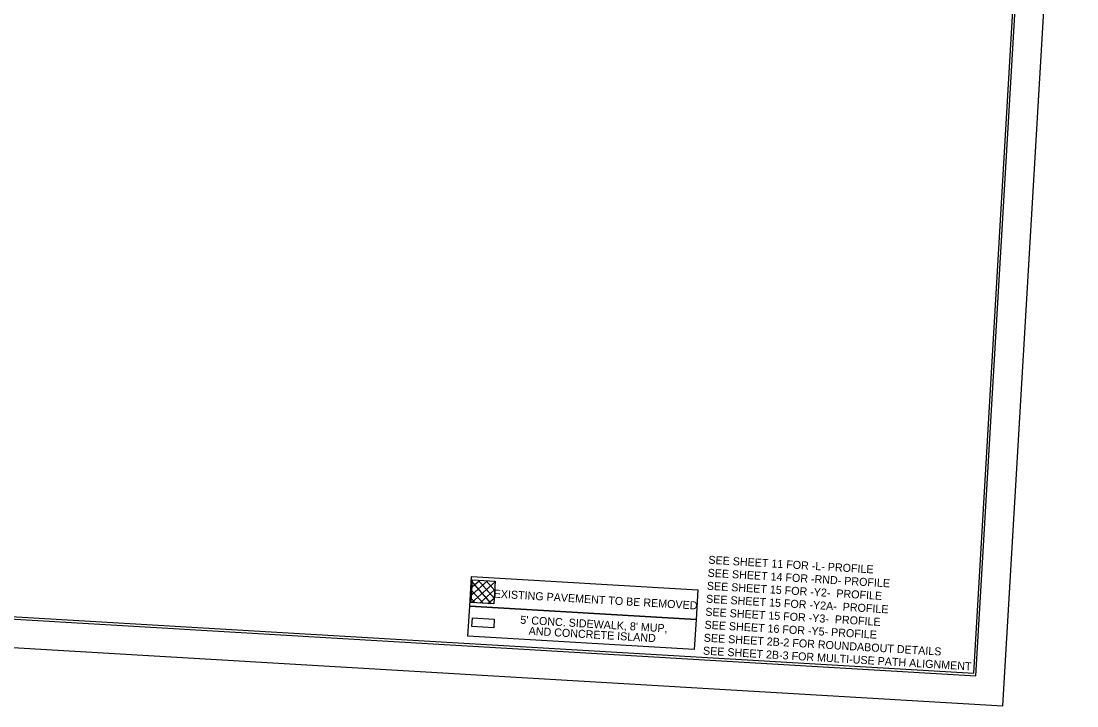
# Model space of a CAD drawing. Extents: x 2012250 to 2014096, y 444445 to 445643.
# Drawn here: x 2013173 to 2014096, y 444445 to 445044 of the extents above; entities that cross this region are included whole.
import ezdxf

# ---------------------------------------------------------------- set-up
doc = ezdxf.new("R2010")
doc.units = 0
for name, color, linetype in [('Exist PHM Road to be Removed Shape', 7, 'Continuous'), ('Old_Level_45', 7, 'Continuous'), ('Prop DSN Text', 7, 'Continuous'), ('Scratch_Level_0', 7, 'Continuous'), ('Sheet Clip Boundary CELL', 7, 'Continuous'), ('Sheet Plot Border Outside CELL', 7, 'Continuous'), ('Sheet Profile Grid Minor CELL', 7, 'Continuous')]:
    doc.layers.add(name, color=color, linetype=linetype)

msp = doc.modelspace()

# ---------------------------------------------------------------- linework, layer by layer
at = {"layer": 'Exist PHM Road to be Removed Shape'}
for p, q in [((2013566.98, 444535.35), (2013587.37, 444553.46)), ((2013567.02, 444542.07), (2013580.87, 444554.37)), ((2013567.44, 444549.13), (2013573.81, 444554.79)), ((2013567.65, 444552.81), (2013584.07, 444534.34)), ((2013572.52, 444554.87), (2013586.52, 444539.1)), ((2013579.58, 444554.45), (2013586.94, 444546.16)), ((2013586.64, 444554.03), (2013587.36, 444553.22)), ((2013566.82, 444538.69), (2013569.95, 444535.17)), ((2013567.24, 444545.75), (2013577.01, 444534.76)), ((2013574.04, 444534.93), (2013586.95, 444546.41)), ((2013581.1, 444534.52), (2013586.54, 444539.35))]:
    msp.add_line(p, q, dxfattribs=at)
msp.add_lwpolyline([(2013567.79, 444555.14), (2013587.4, 444553.99), (2013586.24, 444534.21), (2013566.63, 444535.37)], close=True, dxfattribs=at)
at = {"layer": 'Old_Level_45'}
msp.add_lwpolyline([(2014069.67, 445519.6), (2012572.27, 445607.87), (2012510.48, 444559.69), (2014007.88, 444471.42)], close=True, dxfattribs=at)
at = {"layer": 'Scratch_Level_0'}
msp.add_lwpolyline([(2013567.67, 444522), (2013586.68, 444520.88), (2013586.23, 444513.27), (2013567.22, 444514.39)], close=True, dxfattribs=at)
at = {"layer": 'Sheet Clip Boundary CELL'}
msp.add_lwpolyline([(2013668.15, 445541.27), (2012675.35, 445599.79), (2012666.5, 445450.87), (2012644.05, 445070.04), (2012629.92, 444830.46), (2012620.01, 444659.47), (2012673.15, 444619.9), (2012617.31, 444617.99), (2012613.72, 444555.61), (2014006.01, 444473.54), (2014041.96, 445083.42), (2013915.76, 445258.44), (2013612.37, 445329.9), (2013615.96, 445390.93), (2013652.41, 445436.93), (2013664.23, 445474.69)], close=True, dxfattribs=at)
at = {"layer": 'Sheet Plot Border Outside CELL'}
msp.add_lwpolyline([(2012334.32, 444545.03), (2014031.37, 444445), (2014096.1, 445543.09), (2012399.05, 445643.13)], close=True, dxfattribs=at)
at = {"layer": 'Sheet Profile Grid Minor CELL'}
for points in [[(2013566.8, 444558.14), (2013764.65, 444546.47), (2013763.12, 444520.46), (2013565.27, 444532.12)], [(2013565.27, 444532.12), (2013763.12, 444520.46), (2013761.58, 444494.44), (2013563.74, 444506.11)]]:
    msp.add_lwpolyline(points, close=True, dxfattribs=at)

# ---------------------------------------------------------------- texts
at = {"layer": 'Prop DSN Text'}
for s, p in [('SEE SHEET 11 FOR -L- PROFILE', (2013773.77, 444569.4)), ('SEE SHEET 14 FOR -RND- PROFILE', (2013773.1, 444558.04)), ('EXISTING PAVEMENT TO BE REMOVED', (2013586.08, 444539.78)), ('SEE SHEET 15 FOR -Y2-  PROFILE', (2013772.43, 444546.69)), ('SEE SHEET 15 FOR -Y2A-  PROFILE', (2013771.76, 444535.33)), ('SEE SHEET 15 FOR -Y3-  PROFILE', (2013771.09, 444523.97)), ("5' CONC. SIDEWALK, 8' MUP,", (2013609.34, 444516.9)), ('SEE SHEET 16 FOR -Y5- PROFILE', (2013770.42, 444512.62)), ('AND CONCRETE ISLAND', (2013616.63, 444507.28)), ('SEE SHEET 2B-2 FOR ROUNDABOUT DETAILS', (2013769.75, 444501.26)), ('SEE SHEET 2B-3 FOR MULTI-USE PATH ALIGNMENT', (2013769.08, 444489.91))]:
    msp.add_text(s, height=7, rotation=356.62643, dxfattribs=at).set_placement(p)

doc.saveas('drawing.dxf')
